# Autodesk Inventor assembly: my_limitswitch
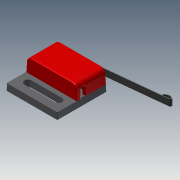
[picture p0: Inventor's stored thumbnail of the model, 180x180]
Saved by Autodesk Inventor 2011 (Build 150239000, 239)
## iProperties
Created: 2010-05
Part Number: my_limitswitch
Document SubType Name: Assembly
Designer: Phil
Author: Phil
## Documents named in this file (4)
- C:\Data Folder\VEX 2011\Inventor Datasets\Unit 2\my_limitswitch.iam
- C:\Data Folder\VEX 2011\Inventor Datasets\Unit 2\LIMIT-SWITCH-MICROSWITCH.ipt
- C:\Data Folder\VEX 2011\Inventor Datasets\Unit 2\LIMIT-SWITCH-BOTTOM.ipt
- C:\Data Folder\VEX 2011\Inventor Datasets\Unit 2\LIMIT-SWITCH-TOP.ipt
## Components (3 placed, 3 different names)
1. LIMIT-SWITCH-MICROSWITCH:1 — Mate:1, Mate:2, Mate:3
2. LIMIT-SWITCH-BOTTOM:1 — Mate:1, Mate:2, Mate:3, Insert:1, Insert:2
3. LIMIT-SWITCH-TOP:1 — Insert:1, Insert:2
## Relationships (5: Mate 3, Insert 2)
- Mate:1: LIMIT-SWITCH-MICROSWITCH:1 ↔ LIMIT-SWITCH-BOTTOM:1
- Mate:2: LIMIT-SWITCH-MICROSWITCH:1 ↔ LIMIT-SWITCH-BOTTOM:1
- Mate:3: LIMIT-SWITCH-MICROSWITCH:1 ↔ LIMIT-SWITCH-BOTTOM:1
- Insert:1: LIMIT-SWITCH-BOTTOM:1 ↔ LIMIT-SWITCH-TOP:1
- Insert:2: LIMIT-SWITCH-BOTTOM:1 ↔ LIMIT-SWITCH-TOP:1
